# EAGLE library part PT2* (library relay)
Miniature Relay SCHRACK 2 pole 12 A DC- or AC-coil Source: http://www.schrack.com/.. 5823.pdf Socked 78602 Source: http://www.schrack.com/.. 5836.pdf
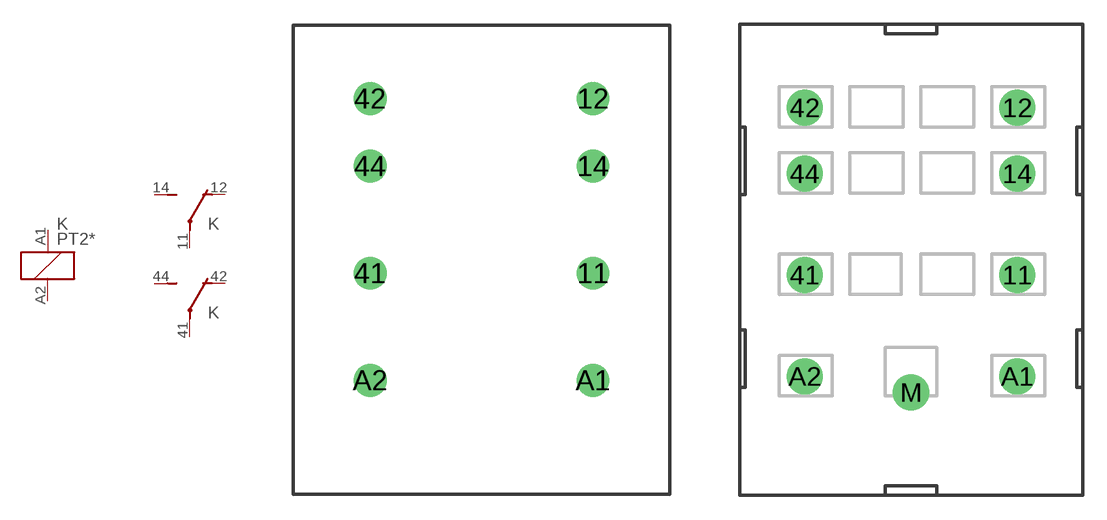
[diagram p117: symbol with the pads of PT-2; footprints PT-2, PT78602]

Designator prefix K; gates 1=K 2=U 3=U

## PT271R06 (OC_FARNELL: unknown; OC_NEWARK: unknown), PT271R12 (OC_FARNELL: unknown; OC_NEWARK: unknown), PT271R24 (OC_FARNELL: unknown; OC_NEWARK: unknown), PT271R48 (OC_FARNELL: unknown; OC_NEWARK: unknown), PT271R60 (OC_FARNELL: unknown; OC_NEWARK: unknown), PT271S15 (OC_FARNELL: unknown; OC_NEWARK: unknown), PT271T30 (OC_FARNELL: unknown; OC_NEWARK: unknown), PT281R06 (OC_FARNELL: unknown; OC_NEWARK: unknown), PT281R12 (OC_FARNELL: unknown; OC_NEWARK: unknown), PT281R24 (OC_FARNELL: unknown; OC_NEWARK: unknown), PT281R48 (OC_FARNELL: unknown; OC_NEWARK: unknown), PT281R60 (OC_FARNELL: unknown; OC_NEWARK: unknown), PT281S15 (OC_FARNELL: unknown; OC_NEWARK: unknown), PT281T30 (OC_FARNELL: unknown; OC_NEWARK: unknown), PT271506 (OC_FARNELL: unknown; OC_NEWARK: unknown), PT271512 (OC_FARNELL: unknown; OC_NEWARK: unknown), PT271524 (OC_FARNELL: unknown; OC_NEWARK: unknown), PT271548 (OC_FARNELL: unknown; OC_NEWARK: unknown), PT271560 (OC_FARNELL: unknown; OC_NEWARK: unknown), PT271615 (MF: TYCO ELECTRONICS; MPN: PT271615; OC_FARNELL: unknown; OC_NEWARK: 96H9720), PT271730 (OC_FARNELL: unknown; OC_NEWARK: unknown), PT281506 (OC_FARNELL: unknown; OC_NEWARK: unknown), PT281512 (OC_FARNELL: unknown; OC_NEWARK: unknown), PT281524 (OC_FARNELL: unknown; OC_NEWARK: unknown), PT281548 (OC_FARNELL: unknown; OC_NEWARK: unknown), PT281560 (OC_FARNELL: unknown; OC_NEWARK: unknown), PT281615 (OC_FARNELL: unknown; OC_NEWARK: unknown), PT281730 (OC_FARNELL: unknown; OC_NEWARK: unknown)  [PT-2]
11  2:P  pas
12  2:O  pas
14  2:S  pas
41  3:P  pas
42  3:O  pas
44  3:S  pas
A1  1:1  pas
A2  1:2  pas

## PT2-78602 (OC_FARNELL: unknown; OC_NEWARK: unknown)  [PT78602]
Pads as for PT-2

## Footprint PT-2 (pad centres in mm)
Miniature Relay SCHRACK 2 pole 12 A DC- or AC-coil Source: http://www.schrack.com/.. 5823.pdf
drill 1.3 round: 11 6.6,6.35; 12 6.6,16.7; 14 6.6,12.7; 41 -6.6,6.35; 42 -6.6,16.7; 44 -6.6,12.7; A1 6.6,0; A2 -6.6,0

## Footprint PT78602 (pad centres in mm)
Accessories Miniature Relay PT SCHRACK Socket with PCB terminals 2 Pol. Source: http://www.schrack.com/.. 5836.pdf
drill 1.5 round: 11 6.6,6.3; 12 6.6,16.7; 14 6.6,12.6; 41 -6.6,6.3; 42 -6.6,16.7; 44 -6.6,12.6; A1 6.6,0; A2 -6.6,0; M 0,-1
